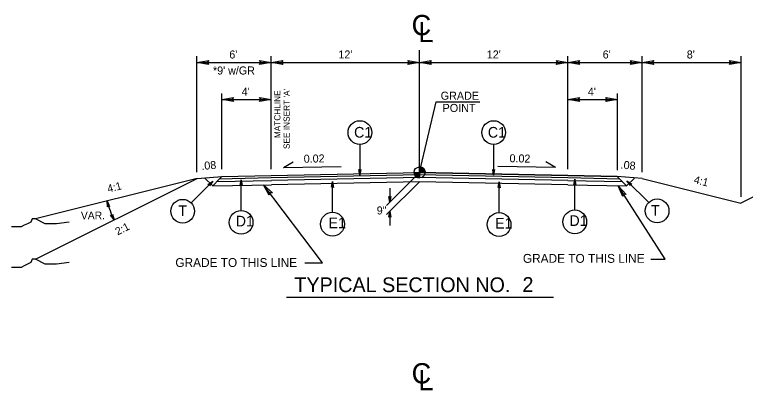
# Model space of a CAD drawing. Extents: x 573771 to 574316, y -53454 to -53190.
# Drawn here: x 574083 to 574201.2, y -53324.5 to -53263.7 of the extents above; entities that cross this region are included whole.
import ezdxf

# ---------------------------------------------------------------- set-up
doc = ezdxf.new("R2010")
doc.units = 0
for name, color, linetype in [('Typical Detail Wedge2 CELL', 7, 'Continuous'), ('Typical Grade Point Symbol CELL', 7, 'Continuous'), ('Typical ID Circle CELL', 7, 'Continuous'), ('Typical Pavement Slope CELL', 7, 'Continuous'), ('Typical Pavement Slope Information CELL', 7, 'Continuous'), ('Typical Shoulder Slope CELL', 7, 'Continuous'), ('Typical Shoulder Slope Information CELL', 7, 'Continuous'), ('Typical Slope Point Local CELL', 7, 'Continuous'), ('Typical Terminator CELL', 7, 'Continuous'), ('Typical Text Centerline CELL', 7, 'Continuous'), ('Typical Text General CELL', 7, 'Continuous'), ('Typical Text Grade Point CELL', 7, 'Continuous'), ('Typical Text ID Circle CELL', 7, 'Continuous'), ('Typical Text Label CELL', 7, 'Continuous')]:
    doc.layers.add(name, color=color, linetype=linetype)

msp = doc.modelspace()

# ---------------------------------------------------------------- linework, layer by layer
at = {"layer": 'Typical Grade Point Symbol CELL'}
for p, q in [((574148.51, -53289.25), (574148.51, -53288.35)), ((574147.62, -53289.25), (574148.51, -53289.25)), ((574149.41, -53289.25), (574148.51, -53289.25)), ((574148.51, -53290.14), (574148.51, -53289.25)), ((574148.51, -53289.25), (574148.51, -53290.14))]:
    msp.add_line(p, q, dxfattribs=at)
for points in [[(574148.52, -53288.35), (574148.52, -53288.35), (574148.52, -53289.25)], [(574148.54, -53288.35), (574148.54, -53289.25)], [(574148.56, -53288.35), (574148.56, -53289.25)], [(574148.57, -53288.35), (574148.57, -53289.25)], [(574148.59, -53288.36), (574148.59, -53289.25)], [(574148.61, -53288.36), (574148.61, -53289.25)], [(574148.63, -53288.36), (574148.63, -53289.25)], [(574148.64, -53288.36), (574148.64, -53289.25)], [(574148.66, -53288.36), (574148.66, -53289.25)], [(574148.68, -53288.37), (574148.68, -53289.25)], [(574148.7, -53288.37), (574148.7, -53289.25)], [(574148.72, -53288.38), (574148.72, -53289.25)], [(574148.73, -53288.38), (574148.73, -53289.25)], [(574148.75, -53288.39), (574148.75, -53289.25)], [(574148.77, -53288.39), (574148.77, -53289.25)], [(574148.79, -53288.4), (574148.79, -53289.25)], [(574148.81, -53288.4), (574148.81, -53289.25)], [(574148.82, -53288.41), (574148.82, -53289.25)], [(574148.84, -53288.42), (574148.84, -53289.25)], [(574148.86, -53288.42), (574148.86, -53289.25)], [(574148.88, -53288.43), (574148.88, -53289.25)], [(574148.9, -53288.44), (574148.9, -53289.25)], [(574148.91, -53288.45), (574148.91, -53289.25)], [(574148.93, -53288.46), (574148.93, -53289.25)], [(574148.95, -53288.47), (574148.95, -53289.25)], [(574148.97, -53288.48), (574148.97, -53289.25)], [(574148.98, -53288.49), (574148.98, -53289.25)], [(574149, -53288.5), (574149, -53289.25)], [(574149.02, -53288.51), (574149.02, -53289.25)], [(574149.04, -53288.52), (574149.04, -53289.25)], [(574149.06, -53288.54), (574149.06, -53289.25)], [(574149.07, -53288.55), (574149.07, -53289.25)], [(574149.09, -53288.57), (574149.09, -53289.25)], [(574149.11, -53288.58), (574149.11, -53289.25)], [(574149.13, -53288.6), (574149.13, -53289.25)], [(574149.15, -53288.62), (574149.15, -53289.25)], [(574149.16, -53288.63), (574149.16, -53289.25)], [(574149.18, -53288.65), (574149.18, -53289.25)], [(574149.2, -53288.68), (574149.2, -53289.25)], [(574149.22, -53288.7), (574149.22, -53289.25)], [(574149.24, -53288.72), (574149.24, -53289.25)], [(574149.25, -53288.75), (574149.25, -53289.25)], [(574149.27, -53288.78), (574149.27, -53289.25)], [(574149.29, -53288.81), (574149.29, -53289.25)], [(574149.31, -53288.84), (574149.31, -53289.25)], [(574149.33, -53288.88), (574149.33, -53289.25)], [(574149.34, -53288.92), (574149.34, -53289.25)], [(574147.62, -53289.25), (574147.62, -53289.34)], [(574147.64, -53289.25), (574147.64, -53289.45)], [(574147.66, -53289.25), (574147.66, -53289.51)], [(574147.67, -53289.25), (574147.67, -53289.57)], [(574147.69, -53289.25), (574147.69, -53289.61)], [(574147.71, -53289.25), (574147.71, -53289.65)], [(574147.73, -53289.25), (574147.73, -53289.68)], [(574147.75, -53289.25), (574147.75, -53289.71)], [(574147.76, -53289.25), (574147.76, -53289.74)], [(574147.78, -53289.25), (574147.78, -53289.77)], [(574147.8, -53289.25), (574147.8, -53289.79)], [(574147.82, -53289.25), (574147.82, -53289.81)], [(574147.84, -53289.25), (574147.84, -53289.83)], [(574147.85, -53289.25), (574147.85, -53289.85)], [(574147.87, -53289.25), (574147.87, -53289.87)], [(574147.89, -53289.25), (574147.89, -53289.89)], [(574147.91, -53289.25), (574147.91, -53289.91)], [(574147.92, -53289.25), (574147.92, -53289.92)], [(574147.94, -53289.25), (574147.94, -53289.94)], [(574147.96, -53289.25), (574147.96, -53289.95)], [(574147.98, -53289.25), (574147.98, -53289.97)], [(574148, -53289.25), (574148, -53289.98)], [(574148.01, -53289.25), (574148.01, -53289.99)], [(574148.03, -53289.25), (574148.03, -53290)], [(574148.05, -53289.25), (574148.05, -53290.01)], [(574148.07, -53289.25), (574148.07, -53290.02)], [(574148.09, -53289.25), (574148.09, -53290.03)], [(574148.1, -53289.25), (574148.1, -53290.04)], [(574148.12, -53289.25), (574148.12, -53290.05)], [(574148.14, -53289.25), (574148.14, -53290.06)], [(574148.16, -53289.25), (574148.16, -53290.07)], [(574148.18, -53289.25), (574148.18, -53290.08)], [(574148.19, -53289.25), (574148.19, -53290.08)], [(574148.21, -53289.25), (574148.21, -53290.09)], [(574148.23, -53289.25), (574148.23, -53290.1)], [(574148.25, -53289.25), (574148.25, -53290.1)], [(574148.26, -53289.25), (574148.26, -53290.11)], [(574148.28, -53289.25), (574148.28, -53290.11)], [(574148.3, -53289.25), (574148.3, -53290.12)], [(574148.32, -53289.25), (574148.32, -53290.12)], [(574148.34, -53289.25), (574148.34, -53290.12)], [(574148.35, -53289.25), (574148.35, -53290.13)], [(574148.37, -53289.25), (574148.37, -53290.13)], [(574148.39, -53289.25), (574148.39, -53290.13)], [(574148.41, -53289.25), (574148.41, -53290.14)], [(574148.43, -53289.25), (574148.43, -53290.14)], [(574148.44, -53289.25), (574148.44, -53290.14)], [(574148.46, -53289.25), (574148.46, -53290.14)], [(574148.48, -53289.25), (574148.48, -53290.14)], [(574148.5, -53289.25), (574148.5, -53290.14), (574148.5, -53290.14)], [(574149.36, -53288.97), (574149.36, -53289.25)], [(574149.38, -53289.03), (574149.38, -53289.25)], [(574149.4, -53289.12), (574149.4, -53289.25)]]:
    msp.add_lwpolyline(points, dxfattribs=at)
msp.add_circle((574148.51, -53289.25), 0.895, dxfattribs=at)
for start, end in [(359.9905, 89.9905), (179.9905, 269.9905)]:
    msp.add_arc((574148.51, -53289.25), 0.895, start, end, dxfattribs=at)
at = {"layer": 'Typical ID Circle CELL'}
for p, q in [((574138.86, -53284.73), (574138.86, -53289.7)), ((574160.5, -53284.73), (574160.5, -53289.7)), ((574111.55, -53294.16), (574115.07, -53290.64)), ((574119.65, -53295.4), (574119.65, -53290.43)), ((574134.43, -53295.69), (574134.43, -53290.72)), ((574161.37, -53295.75), (574161.37, -53290.78)), ((574173.62, -53295.32), (574173.62, -53290.35)), ((574185.58, -53294.1), (574182.06, -53290.59))]:
    msp.add_line(p, q, dxfattribs=at)
for centre in [(574138.86, -53282.81), (574160.5, -53282.81), (574110.19, -53295.52), (574186.94, -53295.46), (574119.65, -53297.32), (574134.43, -53297.61), (574161.37, -53297.67), (574173.62, -53297.24)]:
    msp.add_circle(centre, 1.92, dxfattribs=at)
at = {"layer": 'Typical Pavement Slope CELL'}
for p in [(574124.52, -53289.73), (574172.5, -53289.73)]:
    msp.add_line(p, (574148.51, -53289.25), dxfattribs=at)
at = {"layer": 'Typical Pavement Slope Information CELL'}
for p, q in [((574148.51, -53289.25), (574148.51, -53269.48)), ((574112.51, -53289.22), (574112.51, -53270.48)), ((574124.51, -53288.73), (574124.51, -53270.48)), ((574172.51, -53288.73), (574172.51, -53270.48)), ((574184.51, -53289.22), (574184.51, -53270.48)), ((574200.51, -53293.2), (574200.51, -53270.48)), ((574112.51, -53271.48), (574124.51, -53271.48)), ((574124.51, -53271.48), (574148.51, -53271.48)), ((574148.51, -53271.48), (574172.51, -53271.48)), ((574172.51, -53271.48), (574184.51, -53271.48)), ((574184.51, -53271.48), (574200.51, -53271.48)), ((574116.51, -53288.73), (574116.51, -53276.48)), ((574180.51, -53288.89), (574180.51, -53276.48)), ((574116.51, -53277.48), (574124.51, -53277.48)), ((574172.51, -53277.48), (574180.51, -53277.48)), ((574126.51, -53288.46), (574128.07, -53287.51)), ((574170.52, -53288.46), (574168.95, -53287.51)), ((574126.51, -53288.46), (574135.83, -53288.27)), ((574170.52, -53288.46), (574161.2, -53288.27)), ((574116.11, -53290.32), (574116.52, -53289.89)), ((574116.52, -53289.89), (574124.52, -53289.73)), ((574124.52, -53289.73), (574148.51, -53289.25)), ((574148.51, -53289.66), (574124.52, -53290.14)), ((574148.51, -53290.08), (574124.54, -53290.56)), ((574143.19, -53294.57), (574148.51, -53289.25)), ((574148.51, -53289.25), (574172.5, -53289.73)), ((574172.5, -53290.14), (574148.51, -53289.66)), ((574172.5, -53290.56), (574148.51, -53290.08)), ((574172.5, -53289.73), (574180.5, -53289.89)), ((574180.5, -53289.89), (574180.91, -53290.32)), ((574113.7, -53290.13), (574115.05, -53291.42)), ((574115.05, -53291.42), (574116.11, -53290.32)), ((574115.05, -53291.42), (574124.55, -53291.23)), ((574115.71, -53290.74), (574124.54, -53290.56)), ((574124.52, -53290.14), (574116.11, -53290.32)), ((574148.51, -53290.75), (574124.55, -53291.23)), ((574143.18, -53296.07), (574148.5, -53290.75)), ((574172.5, -53291.23), (574148.51, -53290.75)), ((574180.91, -53290.32), (574172.5, -53290.14)), ((574172.5, -53290.56), (574181.32, -53290.74)), ((574172.5, -53291.23), (574181.97, -53291.42)), ((574181.97, -53291.42), (574180.91, -53290.32)), ((574183.32, -53290.13), (574181.97, -53291.42)), ((574143.69, -53291.78), (574143.69, -53294.07)), ((574143.69, -53295.56), (574143.69, -53297.84))]:
    msp.add_line(p, q, dxfattribs=at)
at = {"layer": 'Typical Shoulder Slope CELL'}
for p, q in [((574112.52, -53290.22), (574116.52, -53289.89)), ((574116.52, -53289.89), (574124.52, -53289.73)), ((574180.5, -53289.89), (574172.5, -53289.73)), ((574184.5, -53290.22), (574180.5, -53289.89))]:
    msp.add_line(p, q, dxfattribs=at)
at = {"layer": 'Typical Slope Point Local CELL'}
for p, q in [((574216.4, -53286.27), (574200.5, -53294.22)), ((574112.52, -53290.22), (574086.39, -53296.76)), ((574086.39, -53303.29), (574112.52, -53290.22)), ((574184.5, -53290.22), (574200.5, -53294.22))]:
    msp.add_line(p, q, dxfattribs=at)
for points in [[(574091.83, -53297.28), (574089.76, -53297.54), (574089.24, -53297.54), (574088.46, -53297.54), (574087.94, -53297.54), (574087.42, -53297.28), (574086.91, -53297.02), (574086.39, -53296.76), (574085.87, -53296.76), (574085.61, -53297.28), (574085.09, -53297.54), (574084.57, -53297.8), (574084.05, -53298.06), (574083.53, -53298.06), (574083.02, -53298.06), (574082.5, -53298.06)], [(574091.83, -53303.81), (574089.76, -53304.07), (574089.24, -53304.07), (574088.46, -53304.07), (574087.94, -53304.07), (574087.42, -53303.81), (574086.91, -53303.55), (574086.39, -53303.29), (574085.87, -53303.29), (574085.61, -53303.81), (574085.09, -53304.07), (574084.57, -53304.33), (574084.05, -53304.59), (574083.53, -53304.59), (574083.02, -53304.59), (574082.5, -53304.59)]]:
    msp.add_lwpolyline(points, dxfattribs=at)
msp.add_arc((574112.52, -53290.22), 15, 194.0362, 206.5659, dxfattribs=at)
at = {"layer": 'Typical Terminator CELL'}
for points in [[(574114.39, -53271.8), (574112.51, -53271.48), (574114.4, -53271.15), (574114.16, -53271.48)], [(574122.64, -53271.16), (574124.51, -53271.48), (574122.63, -53271.81), (574122.87, -53271.48)], [(574126.39, -53271.8), (574124.51, -53271.48), (574126.4, -53271.15), (574126.16, -53271.48)], [(574146.64, -53271.16), (574148.51, -53271.48), (574146.63, -53271.81), (574146.87, -53271.48)], [(574150.39, -53271.8), (574148.51, -53271.48), (574150.4, -53271.15), (574150.16, -53271.48)], [(574170.64, -53271.16), (574172.51, -53271.48), (574170.63, -53271.81), (574170.87, -53271.48)], [(574174.39, -53271.8), (574172.51, -53271.48), (574174.4, -53271.15), (574174.16, -53271.48)], [(574182.64, -53271.16), (574184.51, -53271.48), (574182.63, -53271.81), (574182.87, -53271.48)], [(574186.39, -53271.8), (574184.51, -53271.48), (574186.4, -53271.15), (574186.16, -53271.48)], [(574198.64, -53271.16), (574200.51, -53271.48), (574198.63, -53271.81), (574198.87, -53271.48)], [(574118.39, -53277.8), (574116.51, -53277.48), (574118.4, -53277.15), (574118.16, -53277.48)], [(574122.64, -53277.16), (574124.51, -53277.48), (574122.63, -53277.81), (574122.87, -53277.48)], [(574174.39, -53277.8), (574172.51, -53277.48), (574174.4, -53277.15), (574174.16, -53277.48)], [(574178.64, -53277.16), (574180.51, -53277.48), (574178.63, -53277.81), (574178.87, -53277.48)], [(574139.02, -53288.77), (574138.86, -53289.7), (574138.7, -53288.76), (574138.86, -53288.88)], [(574160.66, -53288.77), (574160.5, -53289.7), (574160.34, -53288.76), (574160.5, -53288.88)], [(574114.29, -53291.19), (574115.07, -53290.64), (574114.52, -53291.43), (574114.48, -53291.23)], [(574119.49, -53291.37), (574119.65, -53290.43), (574119.81, -53291.37), (574119.65, -53291.25)], [(574124.17, -53292.94), (574123.29, -53291.25), (574124.7, -53292.55), (574124.29, -53292.56)], [(574134.27, -53291.65), (574134.43, -53290.72), (574134.59, -53291.66), (574134.43, -53291.54)], [(574161.21, -53291.71), (574161.37, -53290.78), (574161.54, -53291.72), (574161.37, -53291.6)], [(574173.46, -53291.29), (574173.62, -53290.35), (574173.79, -53291.29), (574173.62, -53291.17)], [(574182.61, -53291.36), (574182.06, -53290.59), (574182.85, -53291.14), (574182.64, -53291.17)], [(574181.38, -53293.15), (574180.64, -53291.39), (574181.94, -53292.8), (574181.53, -53292.78)], [(574143.85, -53293.13), (574143.69, -53294.07), (574143.52, -53293.13), (574143.69, -53293.25)], [(574098.04, -53294.81), (574097.97, -53293.86), (574098.36, -53294.74), (574098.17, -53294.66)], [(574143.53, -53296.49), (574143.69, -53295.56), (574143.86, -53296.5), (574143.69, -53296.38)], [(574098.83, -53296.02), (574099.11, -53296.93), (574098.54, -53296.16), (574098.74, -53296.2)]]:
    msp.add_lwpolyline(points, close=True, dxfattribs=at)
at = {"layer": 'Typical Text Grade Point CELL'}
for p, q in [((574148.51, -53289.25), (574151.2, -53277.82)), ((574151.2, -53277.82), (574158.28, -53277.82)), ((574132.83, -53303.86), (574123.29, -53291.25)), ((574188.24, -53303.27), (574180.64, -53291.39)), ((574129.93, -53303.86), (574132.83, -53303.86)), ((574185.91, -53303.27), (574188.24, -53303.27))]:
    msp.add_line(p, q, dxfattribs=at)
at = {"layer": 'Typical Text Label CELL'}
msp.add_line((574126.98, -53309.4), (574170.19, -53309.4), dxfattribs=at)

# ---------------------------------------------------------------- texts
at = {"layer": 'Typical Detail Wedge2 CELL'}
for s, p in [("SEE INSERT 'A'", (574127.51, -53285.47)), ('MATCHLINE', (574126.01, -53283.71))]:
    msp.add_text(s, height=1, rotation=90, dxfattribs=at).set_placement(p)
at = {"layer": 'Typical Pavement Slope Information CELL'}
for s, p in [("6'", (574117.74, -53270.83)), ("12'", (574135.39, -53270.83)), ("12'", (574159.39, -53270.83)), ("6'", (574178.14, -53270.83)), ("8'", (574191.74, -53270.83)), ("*9' w/GR", (574115.1, -53273.42)), ("4'", (574119.74, -53276.83)), ("4'", (574175.74, -53276.83)), ('9"', (574141.59, -53296.04))]:
    msp.add_text(s, height=1.295, dxfattribs=at).set_placement(p)
for s, rotation, p in [('0.02 ', 1.1457, (574129.79, -53287.69)), ('0.02', 358.8543, (574163.06, -53287.6))]:
    msp.add_text(s, height=1.295, rotation=rotation, dxfattribs=at).set_placement(p)
at = {"layer": 'Typical Shoulder Slope Information CELL'}
for rotation, p in [(4.7607, (574113.27, -53288.86)), (355.2393, (574181, -53288.63))]:
    msp.add_text('.08', height=1.295, rotation=rotation, dxfattribs=at).set_placement(p)
at = {"layer": 'Typical Slope Point Local CELL'}
for s, rotation, p in [('4:1', 345.9638, (574192.8, -53290.97)), ('4:1', 14.0362, (574098.17, -53292.52)), ('2:1', 26.5659, (574099.67, -53299.45))]:
    msp.add_text(s, height=1.25, rotation=rotation, dxfattribs=at).set_placement(p)
msp.add_text('VAR.', height=1.25, dxfattribs=at).set_placement((574093.73, -53296.83))
at = {"layer": 'Typical Text Centerline CELL'}
for p in [(574147.23, -53267.07), (574147.23, -53323.36)]:
    msp.add_text('C', height=3.28, dxfattribs=at).set_placement(p)
for p in [(574148.32, -53268.19), (574148.32, -53324.48)]:
    msp.add_text('L', height=3.28, rotation=359.9469, dxfattribs=at).set_placement(p)
at = {"layer": 'Typical Text General CELL'}
for p in [(574109.01, -53304.53), (574165.23, -53303.86)]:
    msp.add_text('GRADE TO THIS LINE', height=1.4323, dxfattribs=at).set_placement(p)
at = {"layer": 'Typical Text Grade Point CELL'}
for s, p in [('GRADE', (574151.93, -53277.5)), ('POINT', (574152.24, -53279.48))]:
    msp.add_text(s, height=1.305, dxfattribs=at).set_placement(p)
at = {"layer": 'Typical Text ID Circle CELL'}
for s, p in [('C1', (574137.92, -53283.62)), ('C1', (574159.56, -53283.62)), ('T ', (574109.47, -53296.31)), ('T ', (574185.95, -53296.26)), ('D1', (574118.77, -53297.98)), ('E1', (574133.79, -53298.27)), ('E1', (574160.73, -53298.33)), ('D1', (574172.75, -53297.9))]:
    msp.add_text(s, height=1.722, dxfattribs=at).set_placement(p)
at = {"layer": 'Typical Text Label CELL'}
for s, height, p in [('TYPICAL SECTION NO.  ', 2.3871, (574128.26, -53308.6)), ('2', 2.39, (574165.16, -53308.56))]:
    msp.add_text(s, height=height, dxfattribs=at).set_placement(p)

doc.saveas('drawing.dxf')
